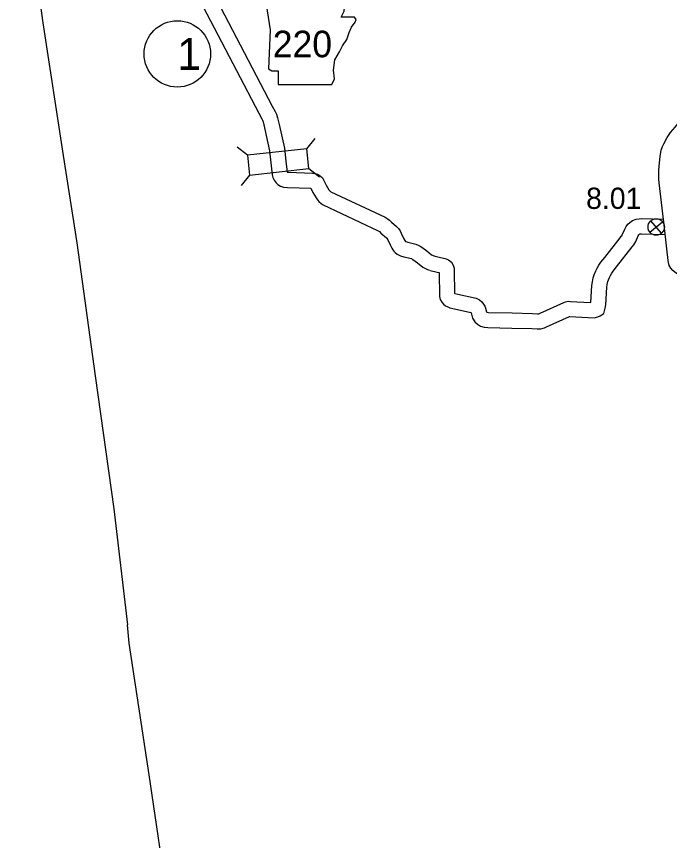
# Model space of a CAD drawing. Extents: x -939622 to -934245, y 1383184 to 1385301.
# Drawn here: x -936461.68 to -936422.74, y 1384633.99 to 1384683.11 of the extents above; entities that cross this region are included whole.
import ezdxf

# ---------------------------------------------------------------- set-up
doc = ezdxf.new("R2010")
doc.units = 0
for name, color, linetype in [('Level 1', 7, 'Continuous'), ('Level 10', 7, 'Continuous'), ('Level 20', 7, 'Continuous'), ('Level 21', 7, 'Continuous'), ('Level 25', 7, 'Continuous'), ('Level 26', 7, 'Continuous'), ('Level 27', 7, 'Continuous')]:
    doc.layers.add(name, color=color, linetype=linetype)

msp = doc.modelspace()

# ---------------------------------------------------------------- linework, layer by layer
at = {"layer": 'Level 1'}
for points in [[(-936461.681, 1384694.182), (-936461.203, 1384690.657), (-936460.102, 1384682.724), (-936458.889, 1384674.816), (-936458.091, 1384669.619), (-936456.988, 1384661.689), (-936455.873, 1384653.762), (-936455.068, 1384646.844)], [(-936451.019, 1384619.545), (-936451.257, 1384621.128), (-936451.394, 1384622.035), (-936452.108, 1384626.797), (-936452.594, 1384629.962), (-936453.761, 1384637.901), (-936454.481, 1384642.618), (-936454.958, 1384645.747), (-936455.068, 1384646.844)]]:
    msp.add_lwpolyline(points, dxfattribs=at)
at = {"layer": 'Level 10'}
for points in [[(-936450.468, 1384685.506), (-936446.44, 1384677.758), (-936446.265, 1384677.434), (-936446.18, 1384677.274), (-936446.112, 1384677.07), (-936446.02, 1384676.661), (-936445.705, 1384675.247), (-936445.613, 1384674.491), (-936445.539, 1384673.824), (-936445.469, 1384673.819), (-936444.026, 1384673.772), (-936443.88, 1384673.746), (-936443.724, 1384673.707), (-936443.571, 1384673.61), (-936443.438, 1384673.478), (-936443.375, 1384673.361), (-936443.214, 1384673.059), (-936443.053, 1384672.781), (-936443.006, 1384672.715), (-936442.995, 1384672.701), (-936442.958, 1384672.668), (-936442.931, 1384672.649), (-936439.697, 1384671.137), (-936439.581, 1384671.071), (-936439.434, 1384670.963), (-936439.329, 1384670.853), (-936439.021, 1384670.59), (-936438.899, 1384670.474), (-936438.812, 1384670.334), (-936438.735, 1384670.192), (-936438.577, 1384669.857), (-936438.525, 1384669.752), (-936438.492, 1384669.702), (-936438.489, 1384669.698), (-936438.461, 1384669.685), (-936438.345, 1384669.648), (-936437.869, 1384669.532), (-936437.739, 1384669.483), (-936437.609, 1384669.414), (-936437.519, 1384669.349), (-936437.22, 1384669.138), (-936436.93, 1384668.905), (-936436.878, 1384668.874), (-936436.836, 1384668.855), (-936436.763, 1384668.83)], [(-936451.217, 1384684.995), (-936447.236, 1384677.336), (-936447.058, 1384677.009), (-936447.01, 1384676.918), (-936446.98, 1384676.828), (-936446.898, 1384676.465), (-936446.593, 1384675.094), (-936446.507, 1384674.387), (-936446.426, 1384673.659), (-936446.387, 1384673.507), (-936446.316, 1384673.348), (-936446.2, 1384673.199), (-936446.088, 1384673.096), (-936445.93, 1384672.996), (-936445.754, 1384672.939), (-936445.52, 1384672.92), (-936444.136, 1384672.875), (-936444.001, 1384672.622), (-936443.81, 1384672.292), (-936443.725, 1384672.173), (-936443.651, 1384672.079), (-936443.519, 1384671.964), (-936443.389, 1384671.87), (-936440.11, 1384670.336), (-936440.07, 1384670.314), (-936440.03, 1384670.284), (-936439.949, 1384670.199), (-936439.623, 1384669.92), (-936439.601, 1384669.899), (-936439.591, 1384669.884), (-936439.54, 1384669.787), (-936439.387, 1384669.464), (-936439.306, 1384669.301), (-936439.236, 1384669.195), (-936439.186, 1384669.124), (-936439.104, 1384669.03), (-936438.973, 1384668.929), (-936438.785, 1384668.844), (-936438.589, 1384668.781), (-936438.135, 1384668.671), (-936438.11, 1384668.661), (-936438.084, 1384668.647), (-936438.041, 1384668.617), (-936437.762, 1384668.419), (-936437.444, 1384668.164), (-936437.297, 1384668.076), (-936437.171, 1384668.019), (-936437.058, 1384667.98)], [(-936422.034, 1384667.69), (-936422.1, 1384667.719), (-936422.258, 1384667.747), (-936422.43, 1384667.869), (-936422.55, 1384667.96), (-936422.655, 1384668.096), (-936422.763, 1384668.262), (-936422.802, 1384668.433), (-936422.822, 1384668.552), (-936422.901, 1384669.252), (-936423.048, 1384670.507), (-936423.366, 1384673.196), (-936423.384, 1384673.403), (-936423.389, 1384673.61), (-936423.379, 1384673.945), (-936423.345, 1384674.379), (-936423.294, 1384674.767), (-936423.232, 1384675.139), (-936423.156, 1384675.351), (-936423.087, 1384675.505), (-936422.878, 1384675.895), (-936422.681, 1384676.191), (-936422.407, 1384676.505), (-936422.253, 1384676.705)], [(-936436.805, 1384668.842), (-936436.4, 1384668.745), (-936436.119, 1384668.685), (-936435.917, 1384668.601), (-936435.751, 1384668.461), (-936435.637, 1384668.288), (-936435.585, 1384668.1), (-936435.574, 1384667.957), (-936435.566, 1384666.607), (-936435.548, 1384666.6), (-936435.363, 1384666.549), (-936434.275, 1384666.322), (-936434.076, 1384666.215), (-936433.934, 1384666.101), (-936433.827, 1384665.961), (-936433.758, 1384665.838), (-936433.717, 1384665.716), (-936433.655, 1384665.498), (-936433.653, 1384665.496), (-936433.629, 1384665.474), (-936433.628, 1384665.473), (-936433.528, 1384665.463), (-936432.128, 1384665.435), (-936430.916, 1384665.397), (-936430.613, 1384665.387), (-936430.546, 1384665.385), (-936430.535, 1384665.389), (-936430.46, 1384665.426), (-936429.052, 1384666.047), (-936428.935, 1384666.094), (-936428.792, 1384666.127), (-936428.647, 1384666.122), (-936428.27, 1384666.092), (-936427.439, 1384666.055), (-936427.371, 1384667.073), (-936427.338, 1384667.295), (-936427.291, 1384667.523), (-936427.235, 1384667.707), (-936427.141, 1384667.938), (-936427.049, 1384668.104), (-936426.953, 1384668.281), (-936426.835, 1384668.451), (-936426.609, 1384668.744), (-936425.684, 1384669.909), (-936425.616, 1384670.004), (-936425.592, 1384670.04), (-936425.572, 1384670.082), (-936425.408, 1384670.432), (-936425.324, 1384670.591), (-936425.218, 1384670.724), (-936425.118, 1384670.825), (-936424.944, 1384670.946), (-936424.736, 1384671.033), (-936424.553, 1384671.051), (-936424.417, 1384671.056), (-936423.109, 1384671.019)], [(-936437.016, 1384667.967), (-936436.599, 1384667.867), (-936436.473, 1384667.84), (-936436.465, 1384666.418), (-936436.417, 1384666.233), (-936436.325, 1384666.072), (-936436.218, 1384665.951), (-936436.099, 1384665.867), (-936435.994, 1384665.81), (-936435.837, 1384665.746), (-936435.573, 1384665.674), (-936434.586, 1384665.467), (-936434.582, 1384665.466), (-936434.576, 1384665.447), (-936434.485, 1384665.127), (-936434.347, 1384664.908), (-936434.184, 1384664.763), (-936434.013, 1384664.647), (-936433.803, 1384664.587), (-936433.583, 1384664.564), (-936432.151, 1384664.536), (-936430.944, 1384664.497), (-936430.642, 1384664.488), (-936430.41, 1384664.48), (-936430.188, 1384664.556), (-936430.078, 1384664.61), (-936428.705, 1384665.217), (-936428.69, 1384665.223), (-936428.326, 1384665.193), (-936427.227, 1384665.144), (-936427.008, 1384665.198), (-936426.88, 1384665.266), (-936426.659, 1384665.405), (-936426.57, 1384665.717), (-936426.547, 1384665.909), (-936426.475, 1384666.976), (-936426.451, 1384667.138), (-936426.418, 1384667.301), (-936426.386, 1384667.406), (-936426.327, 1384667.549), (-936426.26, 1384667.671), (-936426.185, 1384667.808), (-936426.107, 1384667.921), (-936425.9, 1384668.19), (-936424.964, 1384669.368), (-936424.878, 1384669.49), (-936424.808, 1384669.592), (-936424.757, 1384669.701), (-936424.602, 1384670.031), (-936424.568, 1384670.095), (-936424.544, 1384670.126), (-936424.537, 1384670.133), (-936424.511, 1384670.151), (-936424.494, 1384670.152), (-936424.414, 1384670.155), (-936422.995, 1384670.115)]]:
    msp.add_lwpolyline(points, dxfattribs=at)
at = {"layer": 'Level 20'}
for p, q in [((-936444.37, 1384675.222), (-936443.875, 1384675.84)), ((-936447.913, 1384674.83), (-936448.531, 1384675.325)), ((-936444.24, 1384674.041), (-936443.622, 1384673.546)), ((-936447.782, 1384673.65), (-936448.277, 1384673.031))]:
    msp.add_line(p, q, dxfattribs=at)
msp.add_lwpolyline([(-936444.37, 1384675.222), (-936447.913, 1384674.83), (-936447.782, 1384673.65), (-936444.24, 1384674.041)], close=True, dxfattribs=at)
at = {"layer": 'Level 21'}
msp.add_lwpolyline([(-936446.786, 1384683.822), (-936446.557, 1384682.3), (-936446.659, 1384679.99), (-936446.456, 1384679.864), (-936446.075, 1384679.864), (-936446.075, 1384679.052), (-936442.878, 1384679.052), (-936442.725, 1384679.381), (-936442.776, 1384679.914), (-936442.7, 1384680.523), (-936442.421, 1384681.006), (-936442.243, 1384681.361), (-936441.99, 1384681.741), (-936441.837, 1384682.147), (-936441.71, 1384682.477), (-936441.482, 1384682.757), (-936441.431, 1384682.934), (-936441.533, 1384683.061), (-936442.319, 1384683.061), (-936442.142, 1384683.416), (-936442.116, 1384683.645), (-936442.222, 1384683.82)], close=True, dxfattribs=at)
at = {"layer": 'Level 26'}
for p, q in [((-936423.225, 1384670.181), (-936423.847, 1384670.933)), ((-936423.912, 1384670.246), (-936423.16, 1384670.868))]:
    msp.add_line(p, q, dxfattribs=at)
msp.add_circle((-936423.536, 1384670.557), 0.488, dxfattribs=at)
at = {"layer": 'Level 27'}
msp.add_circle((-936452.09, 1384680.875), 1.98, dxfattribs=at)

# ---------------------------------------------------------------- texts
at = {"layer": 'Level 21'}
msp.add_text('220', height=1.584, dxfattribs=at).set_placement((-936446.398, 1384680.674))
at = {"layer": 'Level 25'}
msp.add_text('8.01', height=1.2672, dxfattribs=at).set_placement((-936427.717, 1384671.635))
at = {"layer": 'Level 27'}
msp.add_text('1', height=1.901, dxfattribs=at).set_placement((-936452.09, 1384679.924))

doc.saveas('drawing.dxf')
